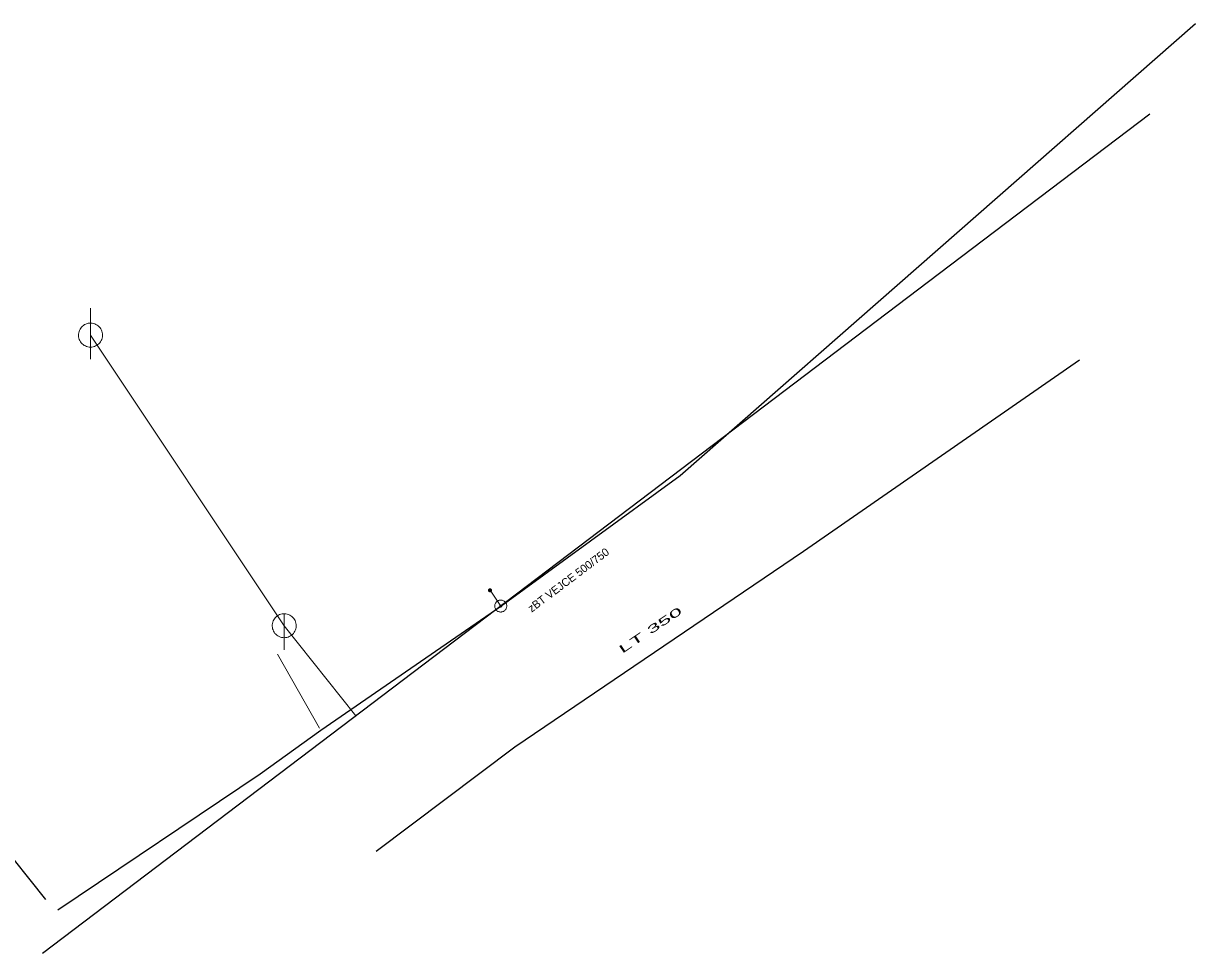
# Model space of a CAD drawing. Extents: x -688296 to -687852, y -973332 to -972816.
# Drawn here: x -687958 to -687860.3, y -973263.6 to -973186.1 of the extents above; entities that cross this region are included whole.
import ezdxf
from ezdxf.enums import TextEntityAlignment as Align

# ---------------------------------------------------------------- set-up
doc = ezdxf.new("R2010")
doc.units = 0
doc.header["$LTSCALE"] = 0.27
for name, color, linetype, lineweight in [('1', 7, 'Continuous', 25), ('11', 7, 'Continuous', 13), ('13', 7, 'Continuous', 13), ('14', 7, 'Continuous', 13), ('17', 7, 'Continuous', 25), ('22', 7, 'Continuous', 13), ('47', 7, 'Continuous', 13), ('9', 7, 'Continuous', 13)]:
    doc.layers.add(name, color=color, linetype=linetype, lineweight=lineweight)

msp = doc.modelspace()

# ---------------------------------------------------------------- linework, layer by layer
at = {"layer": '11'}
for p, q in [((-687952.402, -973209.829), (-687952.402, -973212.078)), ((-687952.402, -973212.078), (-687936.262, -973236.287)), ((-687936.262, -973236.287), (-687930.291, -973243.81))]:
    msp.add_line(p, q, dxfattribs=at)
at = {"layer": '13'}
msp.add_line((-687933.312, -973244.822), (-687936.809, -973238.664), dxfattribs=at)
at = {"layer": '14'}
msp.add_line((-687918.225, -973234.652), (-687919.117, -973233.337), dxfattribs=at)
at = {"layer": '14', "lineweight": 25}
msp.add_lwpolyline([(-687864.146, -973193.666), (-687882.579, -973207.64), (-687956.403, -973263.605)], dxfattribs=at)
at = {"layer": '17'}
msp.add_line((-687956.115, -973259.105), (-687987.568, -973219.849), dxfattribs=at)
for points in [[(-687918.225, -973234.652), (-687903.281, -973223.784), (-687860.339, -973186.109)], [(-687928.615, -973255.081), (-687917.039, -973246.39), (-687893.011, -973230.091), (-687870.011, -973214.129)], [(-687955.131, -973259.958), (-687938.257, -973248.627), (-687933.21, -973245.001), (-687918.225, -973234.652)]]:
    msp.add_lwpolyline(points, dxfattribs=at)
at = {"layer": '22'}
for p, q in [((-687952.402, -973214.078), (-687952.401, -973211.078)), ((-687936.262, -973238.287), (-687936.261, -973235.287))]:
    msp.add_line(p, q, dxfattribs=at)
for points in [[(-687951.402, -973212.078), (-687951.407, -973211.969), (-687951.425, -973211.861), (-687951.455, -973211.755), (-687951.495, -973211.654), (-687951.547, -973211.557), (-687951.609, -973211.467), (-687951.681, -973211.384), (-687951.761, -973211.31), (-687951.849, -973211.244), (-687951.943, -973211.189), (-687952.043, -973211.144), (-687952.148, -973211.111), (-687952.255, -973211.089), (-687952.364, -973211.079), (-687952.474, -973211.081), (-687952.582, -973211.095), (-687952.689, -973211.12), (-687952.792, -973211.157), (-687952.89, -973211.206), (-687952.982, -973211.264), (-687953.068, -973211.333), (-687953.145, -973211.41), (-687953.214, -973211.496), (-687953.273, -973211.588), (-687953.321, -973211.686), (-687953.358, -973211.789), (-687953.384, -973211.896), (-687953.398, -973212.004), (-687953.401, -973212.114), (-687953.391, -973212.223), (-687953.37, -973212.33), (-687953.336, -973212.434), (-687953.292, -973212.534), (-687953.237, -973212.629), (-687953.171, -973212.717), (-687953.097, -973212.797), (-687953.014, -973212.869), (-687952.924, -973212.931), (-687952.828, -973212.983), (-687952.726, -973213.024), (-687952.621, -973213.054), (-687952.513, -973213.072), (-687952.403, -973213.078), (-687952.294, -973213.072), (-687952.186, -973213.054), (-687952.081, -973213.025), (-687951.979, -973212.984), (-687951.882, -973212.932), (-687951.792, -973212.87), (-687951.709, -973212.799), (-687951.634, -973212.719), (-687951.569, -973212.631), (-687951.513, -973212.537), (-687951.469, -973212.437), (-687951.435, -973212.333), (-687951.413, -973212.225), (-687951.403, -973212.116)], [(-687935.262, -973236.287), (-687935.267, -973236.178), (-687935.285, -973236.07), (-687935.315, -973235.964), (-687935.355, -973235.863), (-687935.407, -973235.766), (-687935.469, -973235.676), (-687935.541, -973235.593), (-687935.621, -973235.519), (-687935.709, -973235.453), (-687935.803, -973235.398), (-687935.903, -973235.353), (-687936.008, -973235.32), (-687936.115, -973235.298), (-687936.224, -973235.288), (-687936.334, -973235.29), (-687936.442, -973235.304), (-687936.549, -973235.329), (-687936.652, -973235.366), (-687936.75, -973235.415), (-687936.842, -973235.473), (-687936.928, -973235.542), (-687937.005, -973235.619), (-687937.074, -973235.705), (-687937.133, -973235.797), (-687937.181, -973235.895), (-687937.218, -973235.998), (-687937.244, -973236.105), (-687937.258, -973236.213), (-687937.261, -973236.323), (-687937.251, -973236.432), (-687937.23, -973236.539), (-687937.196, -973236.643), (-687937.152, -973236.743), (-687937.097, -973236.838), (-687937.031, -973236.926), (-687936.957, -973237.006), (-687936.874, -973237.078), (-687936.784, -973237.14), (-687936.688, -973237.192), (-687936.586, -973237.233), (-687936.481, -973237.263), (-687936.373, -973237.281), (-687936.263, -973237.287), (-687936.154, -973237.281), (-687936.046, -973237.263), (-687935.941, -973237.234), (-687935.839, -973237.193), (-687935.742, -973237.141), (-687935.652, -973237.079), (-687935.569, -973237.008), (-687935.494, -973236.928), (-687935.429, -973236.84), (-687935.373, -973236.746), (-687935.329, -973236.646), (-687935.295, -973236.542), (-687935.273, -973236.434), (-687935.263, -973236.325)]]:
    msp.add_lwpolyline(points, close=True, dxfattribs=at)
at = {"layer": '47'}
for points in [[(-687917.803, -973234.382), (-687917.834, -973234.34), (-687917.869, -973234.3), (-687917.907, -973234.266), (-687917.949, -973234.234), (-687917.994, -973234.208), (-687918.043, -973234.186), (-687918.092, -973234.17), (-687918.143, -973234.159), (-687918.194, -973234.153), (-687918.247, -973234.152), (-687918.3, -973234.157), (-687918.351, -973234.168), (-687918.4, -973234.184), (-687918.448, -973234.205), (-687918.494, -973234.23), (-687918.536, -973234.261), (-687918.576, -973234.296), (-687918.611, -973234.335), (-687918.642, -973234.376), (-687918.668, -973234.421), (-687918.69, -973234.47), (-687918.707, -973234.519), (-687918.718, -973234.571), (-687918.724, -973234.622), (-687918.724, -973234.674), (-687918.719, -973234.727), (-687918.708, -973234.778), (-687918.692, -973234.827), (-687918.671, -973234.875), (-687918.646, -973234.921), (-687918.615, -973234.963), (-687918.58, -973235.003), (-687918.542, -973235.039), (-687918.5, -973235.069), (-687918.455, -973235.095), (-687918.407, -973235.117), (-687918.357, -973235.134), (-687918.306, -973235.145), (-687918.254, -973235.151), (-687918.202, -973235.151), (-687918.149, -973235.146), (-687918.099, -973235.136), (-687918.049, -973235.119), (-687918.001, -973235.098), (-687917.955, -973235.073), (-687917.913, -973235.042), (-687917.873, -973235.007), (-687917.838, -973234.97), (-687917.807, -973234.927), (-687917.781, -973234.882), (-687917.759, -973234.834), (-687917.743, -973234.785), (-687917.731, -973234.734), (-687917.726, -973234.682), (-687917.725, -973234.629), (-687917.73, -973234.576), (-687917.741, -973234.526), (-687917.757, -973234.476), (-687917.778, -973234.428)], [(-687918.155, -973234.607), (-687918.16, -973234.6), (-687918.166, -973234.594), (-687918.172, -973234.588), (-687918.179, -973234.583), (-687918.187, -973234.579), (-687918.195, -973234.576), (-687918.203, -973234.572), (-687918.211, -973234.57), (-687918.22, -973234.57), (-687918.228, -973234.57), (-687918.237, -973234.571), (-687918.245, -973234.572), (-687918.253, -973234.575), (-687918.261, -973234.578), (-687918.269, -973234.582), (-687918.276, -973234.587), (-687918.282, -973234.593), (-687918.288, -973234.599), (-687918.293, -973234.606), (-687918.297, -973234.614), (-687918.3, -973234.622), (-687918.304, -973234.63), (-687918.306, -973234.638), (-687918.307, -973234.647), (-687918.306, -973234.655), (-687918.305, -973234.664), (-687918.304, -973234.672), (-687918.301, -973234.68), (-687918.298, -973234.688), (-687918.294, -973234.696), (-687918.289, -973234.703), (-687918.283, -973234.709), (-687918.277, -973234.715), (-687918.27, -973234.72), (-687918.262, -973234.724), (-687918.255, -973234.728), (-687918.246, -973234.731), (-687918.238, -973234.733), (-687918.229, -973234.734), (-687918.221, -973234.733), (-687918.212, -973234.732), (-687918.204, -973234.731), (-687918.196, -973234.728), (-687918.188, -973234.725), (-687918.18, -973234.721), (-687918.173, -973234.716), (-687918.167, -973234.71), (-687918.161, -973234.704), (-687918.156, -973234.697), (-687918.152, -973234.689), (-687918.148, -973234.682), (-687918.145, -973234.673), (-687918.143, -973234.665), (-687918.143, -973234.656), (-687918.143, -973234.648), (-687918.144, -973234.639), (-687918.145, -973234.631), (-687918.148, -973234.623), (-687918.151, -973234.615)]]:
    msp.add_lwpolyline(points, close=True, dxfattribs=at)
at = {"layer": '9'}
for points in [[(-687919.243, -973233.337), (-687919.243, -973233.35), (-687919.24, -973233.363), (-687919.238, -973233.376), (-687919.233, -973233.388), (-687919.227, -973233.4), (-687919.22, -973233.411), (-687919.212, -973233.421), (-687919.201, -973233.431), (-687919.191, -973233.439), (-687919.181, -973233.446), (-687919.169, -973233.452), (-687919.157, -973233.457), (-687919.144, -973233.46), (-687919.13, -973233.462), (-687919.118, -973233.464), (-687919.105, -973233.463), (-687919.092, -973233.461), (-687919.079, -973233.458), (-687919.066, -973233.453), (-687919.054, -973233.447), (-687919.044, -973233.44), (-687919.034, -973233.432), (-687919.024, -973233.422), (-687919.016, -973233.412), (-687919.009, -973233.401), (-687919.003, -973233.389), (-687918.998, -973233.377), (-687918.995, -973233.364), (-687918.993, -973233.351), (-687918.99, -973233.338), (-687918.992, -973233.325), (-687918.994, -973233.312), (-687918.997, -973233.299), (-687919.002, -973233.287), (-687919.007, -973233.275), (-687919.015, -973233.264), (-687919.022, -973233.254), (-687919.032, -973233.244), (-687919.043, -973233.236), (-687919.054, -973233.229), (-687919.066, -973233.223), (-687919.078, -973233.218), (-687919.091, -973233.215), (-687919.103, -973233.213), (-687919.117, -973233.212), (-687919.13, -973233.212), (-687919.142, -973233.214), (-687919.156, -973233.217), (-687919.168, -973233.222), (-687919.179, -973233.228), (-687919.191, -973233.235), (-687919.201, -973233.243), (-687919.211, -973233.253), (-687919.218, -973233.263), (-687919.226, -973233.274), (-687919.232, -973233.286), (-687919.237, -973233.298), (-687919.24, -973233.311), (-687919.242, -973233.324)], [(-687919.223, -973233.337), (-687919.223, -973233.348), (-687919.222, -973233.359), (-687919.218, -973233.37), (-687919.215, -973233.38), (-687919.21, -973233.39), (-687919.204, -973233.399), (-687919.196, -973233.408), (-687919.189, -973233.416), (-687919.179, -973233.423), (-687919.171, -973233.429), (-687919.161, -973233.434), (-687919.151, -973233.438), (-687919.14, -973233.441), (-687919.129, -973233.444), (-687919.118, -973233.444), (-687919.107, -973233.444), (-687919.096, -973233.442), (-687919.085, -973233.439), (-687919.075, -973233.435), (-687919.065, -973233.43), (-687919.056, -973233.424), (-687919.047, -973233.417), (-687919.039, -973233.409), (-687919.032, -973233.4), (-687919.026, -973233.391), (-687919.021, -973233.381), (-687919.017, -973233.371), (-687919.014, -973233.36), (-687919.012, -973233.349), (-687919.011, -973233.338), (-687919.011, -973233.327), (-687919.012, -973233.316), (-687919.016, -973233.305), (-687919.02, -973233.295), (-687919.025, -973233.285), (-687919.031, -973233.276), (-687919.038, -973233.267), (-687919.046, -973233.259), (-687919.054, -973233.252), (-687919.064, -973233.246), (-687919.074, -973233.241), (-687919.083, -973233.237), (-687919.095, -973233.234), (-687919.105, -973233.232), (-687919.117, -973233.232), (-687919.128, -973233.231), (-687919.139, -973233.233), (-687919.15, -973233.236), (-687919.159, -973233.24), (-687919.169, -973233.245), (-687919.179, -973233.251), (-687919.188, -973233.258), (-687919.196, -973233.266), (-687919.203, -973233.275), (-687919.208, -973233.284), (-687919.213, -973233.294), (-687919.218, -973233.304), (-687919.221, -973233.315), (-687919.223, -973233.326)], [(-687919.204, -973233.337), (-687919.204, -973233.346), (-687919.203, -973233.355), (-687919.2, -973233.364), (-687919.196, -973233.372), (-687919.193, -973233.38), (-687919.188, -973233.388), (-687919.181, -973233.395), (-687919.176, -973233.401), (-687919.169, -973233.407), (-687919.161, -973233.412), (-687919.152, -973233.416), (-687919.145, -973233.419), (-687919.136, -973233.422), (-687919.127, -973233.423), (-687919.118, -973233.425), (-687919.108, -973233.424), (-687919.1, -973233.423), (-687919.091, -973233.42), (-687919.083, -973233.417), (-687919.075, -973233.413), (-687919.066, -973233.408), (-687919.059, -973233.402), (-687919.054, -973233.396), (-687919.048, -973233.389), (-687919.043, -973233.381), (-687919.039, -973233.373), (-687919.036, -973233.365), (-687919.032, -973233.356), (-687919.032, -973233.347), (-687919.029, -973233.338), (-687919.031, -973233.329), (-687919.032, -973233.32), (-687919.034, -973233.311), (-687919.038, -973233.303), (-687919.042, -973233.295), (-687919.047, -973233.287), (-687919.053, -973233.28), (-687919.059, -973233.274), (-687919.066, -973233.268), (-687919.074, -973233.263), (-687919.081, -973233.259), (-687919.09, -973233.256), (-687919.098, -973233.253), (-687919.108, -973233.252), (-687919.117, -973233.251), (-687919.125, -973233.251), (-687919.135, -973233.252), (-687919.144, -973233.255), (-687919.152, -973233.258), (-687919.159, -973233.262), (-687919.168, -973233.267), (-687919.174, -973233.273), (-687919.181, -973233.279), (-687919.186, -973233.286), (-687919.191, -973233.294), (-687919.196, -973233.302), (-687919.199, -973233.31), (-687919.201, -973233.319), (-687919.203, -973233.328)], [(-687919.184, -973233.337), (-687919.184, -973233.344), (-687919.183, -973233.351), (-687919.181, -973233.358), (-687919.179, -973233.364), (-687919.176, -973233.37), (-687919.172, -973233.376), (-687919.168, -973233.382), (-687919.163, -973233.387), (-687919.157, -973233.391), (-687919.151, -973233.395), (-687919.145, -973233.398), (-687919.139, -973233.401), (-687919.132, -973233.402), (-687919.125, -973233.405), (-687919.118, -973233.405), (-687919.11, -973233.405), (-687919.103, -973233.403), (-687919.097, -973233.402), (-687919.091, -973233.399), (-687919.083, -973233.396), (-687919.079, -973233.392), (-687919.073, -973233.388), (-687919.068, -973233.383), (-687919.064, -973233.377), (-687919.059, -973233.371), (-687919.056, -973233.365), (-687919.054, -973233.359), (-687919.052, -973233.352), (-687919.051, -973233.345), (-687919.049, -973233.338), (-687919.049, -973233.331), (-687919.051, -973233.324), (-687919.053, -973233.317), (-687919.056, -973233.311), (-687919.059, -973233.304), (-687919.063, -973233.299), (-687919.066, -973233.293), (-687919.071, -973233.288), (-687919.078, -973233.284), (-687919.083, -973233.28), (-687919.09, -973233.277), (-687919.096, -973233.274), (-687919.103, -973233.272), (-687919.11, -973233.271), (-687919.117, -973233.271), (-687919.124, -973233.271), (-687919.13, -973233.271), (-687919.137, -973233.273), (-687919.144, -973233.276), (-687919.15, -973233.279), (-687919.156, -973233.283), (-687919.162, -973233.287), (-687919.167, -973233.292), (-687919.171, -973233.298), (-687919.174, -973233.303), (-687919.178, -973233.31), (-687919.181, -973233.316), (-687919.181, -973233.323), (-687919.184, -973233.33)], [(-687919.164, -973233.337), (-687919.164, -973233.342), (-687919.164, -973233.347), (-687919.163, -973233.352), (-687919.161, -973233.356), (-687919.159, -973233.361), (-687919.156, -973233.365), (-687919.152, -973233.368), (-687919.149, -973233.372), (-687919.146, -973233.375), (-687919.142, -973233.378), (-687919.137, -973233.38), (-687919.132, -973233.382), (-687919.128, -973233.383), (-687919.123, -973233.385), (-687919.118, -973233.385), (-687919.113, -973233.385), (-687919.108, -973233.384), (-687919.103, -973233.383), (-687919.098, -973233.381), (-687919.093, -973233.379), (-687919.09, -973233.376), (-687919.086, -973233.373), (-687919.083, -973233.369), (-687919.08, -973233.366), (-687919.076, -973233.362), (-687919.075, -973233.357), (-687919.073, -973233.353), (-687919.071, -973233.348), (-687919.071, -973233.343), (-687919.07, -973233.338), (-687919.07, -973233.333), (-687919.071, -973233.328), (-687919.071, -973233.323), (-687919.074, -973233.319), (-687919.076, -973233.314), (-687919.079, -973233.31), (-687919.081, -973233.306), (-687919.085, -973233.303), (-687919.088, -973233.3), (-687919.093, -973233.297), (-687919.098, -973233.295), (-687919.102, -973233.293), (-687919.107, -973233.292), (-687919.112, -973233.291), (-687919.117, -973233.291), (-687919.122, -973233.291), (-687919.127, -973233.292), (-687919.132, -973233.292), (-687919.136, -973233.294), (-687919.141, -973233.296), (-687919.145, -973233.299), (-687919.147, -973233.302), (-687919.152, -973233.305), (-687919.154, -973233.309), (-687919.157, -973233.313), (-687919.159, -973233.318), (-687919.162, -973233.322), (-687919.163, -973233.327), (-687919.164, -973233.332)], [(-687919.144, -973233.337), (-687919.144, -973233.34), (-687919.145, -973233.343), (-687919.144, -973233.345), (-687919.142, -973233.348), (-687919.142, -973233.351), (-687919.14, -973233.353), (-687919.137, -973233.355), (-687919.136, -973233.357), (-687919.134, -973233.359), (-687919.132, -973233.361), (-687919.129, -973233.363), (-687919.125, -973233.364), (-687919.124, -973233.364), (-687919.12, -973233.365), (-687919.118, -973233.365), (-687919.115, -973233.365), (-687919.112, -973233.365), (-687919.108, -973233.364), (-687919.107, -973233.363), (-687919.103, -973233.362), (-687919.102, -973233.36), (-687919.098, -973233.358), (-687919.097, -973233.356), (-687919.096, -973233.354), (-687919.093, -973233.352), (-687919.093, -973233.349), (-687919.091, -973233.346), (-687919.091, -973233.344), (-687919.09, -973233.341), (-687919.088, -973233.338), (-687919.09, -973233.335), (-687919.09, -973233.332), (-687919.091, -973233.329), (-687919.092, -973233.327), (-687919.093, -973233.324), (-687919.095, -973233.322), (-687919.096, -973233.319), (-687919.098, -973233.317), (-687919.101, -973233.316), (-687919.103, -973233.314), (-687919.105, -973233.313), (-687919.108, -973233.312), (-687919.11, -973233.311), (-687919.114, -973233.311), (-687919.117, -973233.31), (-687919.12, -973233.311), (-687919.123, -973233.31), (-687919.125, -973233.312), (-687919.128, -973233.312), (-687919.13, -973233.313), (-687919.132, -973233.315), (-687919.135, -973233.316), (-687919.137, -973233.318), (-687919.139, -973233.321), (-687919.141, -973233.323), (-687919.142, -973233.326), (-687919.142, -973233.328), (-687919.144, -973233.331), (-687919.144, -973233.334)], [(-687919.125, -973233.337), (-687919.125, -973233.339), (-687919.125, -973233.339), (-687919.124, -973233.339), (-687919.124, -973233.341), (-687919.125, -973233.342), (-687919.123, -973233.342), (-687919.123, -973233.342), (-687919.123, -973233.344), (-687919.123, -973233.344), (-687919.122, -973233.345), (-687919.12, -973233.345), (-687919.12, -973233.345), (-687919.12, -973233.346), (-687919.118, -973233.346), (-687919.118, -973233.346), (-687919.117, -973233.346), (-687919.115, -973233.346), (-687919.115, -973233.345), (-687919.115, -973233.345), (-687919.113, -973233.345), (-687919.113, -973233.344), (-687919.113, -973233.344), (-687919.112, -973233.343), (-687919.112, -973233.343), (-687919.11, -973233.342), (-687919.11, -973233.341), (-687919.108, -973233.34), (-687919.108, -973233.34), (-687919.108, -973233.339), (-687919.108, -973233.338), (-687919.108, -973233.337), (-687919.108, -973233.336), (-687919.108, -973233.336), (-687919.11, -973233.335), (-687919.11, -973233.334), (-687919.11, -973233.333), (-687919.11, -973233.333), (-687919.112, -973233.332), (-687919.112, -973233.332), (-687919.113, -973233.331), (-687919.114, -973233.331), (-687919.115, -973233.33), (-687919.115, -973233.33), (-687919.115, -973233.33), (-687919.117, -973233.33), (-687919.118, -973233.33), (-687919.119, -973233.33), (-687919.119, -973233.33), (-687919.12, -973233.331), (-687919.12, -973233.33), (-687919.122, -973233.332), (-687919.122, -973233.332), (-687919.123, -973233.332), (-687919.123, -973233.332), (-687919.124, -973233.334), (-687919.124, -973233.335), (-687919.124, -973233.336), (-687919.125, -973233.336), (-687919.125, -973233.337)]]:
    msp.add_lwpolyline(points, close=True, dxfattribs=at)

# ---------------------------------------------------------------- texts
at = {"layer": '1'}
msp.add_text('zBT VEJCE 500/750 ', height=0.6667, rotation=37, dxfattribs=at).set_placement((-687912.2846, -973232.6732), align=Align.CENTER)
msp.add_text('zBT VEJCE 500/750 ', height=0.6667, rotation=37, dxfattribs=at).set_placement((-687912.2846, -973232.6732), align=Align.CENTER)
msp.add_text('zBT VEJCE 500/750 ', height=0.6667, rotation=37, dxfattribs=at).set_placement((-687912.2846, -973232.6732), align=Align.CENTER)
msp.add_text('zBT VEJCE 500/750 ', height=0.6667, rotation=37, dxfattribs=at).set_placement((-687912.2846, -973232.6732), align=Align.CENTER)
msp.add_text('zBT VEJCE 500/750 ', height=0.6667, rotation=37, dxfattribs=at).set_placement((-687912.2846, -973232.6732), align=Align.CENTER)
at = {"layer": '1', "width": 2.2}
msp.add_text('LT 350', height=0.6667, rotation=34, dxfattribs=at).set_placement((-687905.5724, -973236.9262), align=Align.CENTER)
msp.add_text('LT 350', height=0.6667, rotation=34, dxfattribs=at).set_placement((-687905.5724, -973236.9262), align=Align.CENTER)
msp.add_text('LT 350', height=0.6667, rotation=34, dxfattribs=at).set_placement((-687905.5724, -973236.9262), align=Align.CENTER)
msp.add_text('LT 350', height=0.6667, rotation=34, dxfattribs=at).set_placement((-687905.5724, -973236.9262), align=Align.CENTER)
msp.add_text('LT 350', height=0.6667, rotation=34, dxfattribs=at).set_placement((-687905.5724, -973236.9262), align=Align.CENTER)

doc.saveas('drawing.dxf')
